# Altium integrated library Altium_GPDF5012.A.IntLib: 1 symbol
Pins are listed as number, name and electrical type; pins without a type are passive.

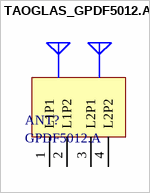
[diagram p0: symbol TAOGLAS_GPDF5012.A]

## TAOGLAS_GPDF5012.A
designator ANT?, comment GPDF5012.A
Passive Multiband High Precision GNSS Stacked Patch Antenna; ComponentLibStatus: Created; MFG: Taoglas; Temp_High: +85C; Temp_Low: -40C
footprint TAOGLAS_GPDF5012.A (Passive Multiband High Precision GNSS Stacked Patch Antenna)
pins: 1 L1P1, 2 L1P2, 3 L2P1, 4 L2P2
